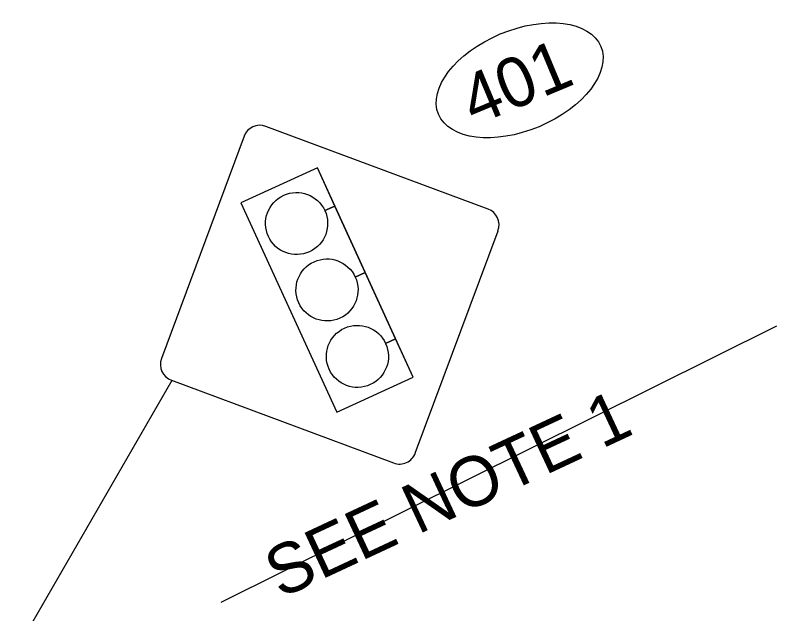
# Model space of a CAD drawing. Extents: x 2096670 to 2098561, y 684033 to 689893.
# Drawn here: x 2097982.4 to 2098166.2, y 685494.3 to 685638.7 of the extents above; entities that cross this region are included whole.
import ezdxf

# ---------------------------------------------------------------- set-up
doc = ezdxf.new("R2010")
doc.units = 0
for name, color, linetype in [('Prop DSN Text', 7, 'Continuous'), ('Prop Sign E One Way_Right CELL', 7, 'Continuous'), ('Prop Sign E Signal Light Ahead CELL', 7, 'Continuous'), ('Scratch_Level_3', 7, 'Continuous')]:
    doc.layers.add(name, color=color, linetype=linetype)

msp = doc.modelspace()

# ---------------------------------------------------------------- linework, layer by layer
at = {"layer": 'Prop Sign E One Way_Right CELL'}
msp.add_ellipse((2098104.11, 685623.02), major_axis=(-19.58, -8.19), ratio=0.571429, dxfattribs=at)
at = {"layer": 'Prop Sign E Signal Light Ahead CELL'}
for p, q in [((2098096.47, 685591.96), (2098042.84, 685611.91)), ((2098037.6, 685609.51), (2098017.65, 685555.88)), ((2098078.92, 685533.08), (2098098.88, 685586.71)), ((2098071.76, 685559.52), (2098071.76, 685559.52)), ((2098071.76, 685559.52), (2098071.76, 685559.52)), ((2098020.18, 685550.58), (2097970.73, 685464.96)), ((2098020.05, 685550.63), (2098073.68, 685530.68))]:
    msp.add_line(p, q, dxfattribs=at)
msp.add_lwpolyline([(2098059.94, 685542.96), (2098078.38, 685551.4), (2098055.27, 685601.9), (2098036.83, 685593.46)], close=True, dxfattribs=at)
for points in [[(2098057.08, 685591.58), (2098059.48, 685592.68), (2098055.27, 685601.9), (2098036.83, 685593.46), (2098059.94, 685542.96), (2098078.38, 685551.4), (2098074.16, 685560.62), (2098071.76, 685559.52)], [(2098057.08, 685591.58), (2098059.48, 685592.68), (2098055.27, 685601.9), (2098036.83, 685593.46), (2098059.94, 685542.96), (2098078.38, 685551.4), (2098074.16, 685560.62), (2098071.76, 685559.52)], [(2098064.42, 685575.55), (2098066.82, 685576.65), (2098059.48, 685592.68), (2098057.08, 685591.58)], [(2098064.42, 685575.55), (2098066.82, 685576.65), (2098059.48, 685592.68), (2098057.08, 685591.58)], [(2098071.76, 685559.52), (2098074.16, 685560.62), (2098066.82, 685576.65), (2098064.42, 685575.55)], [(2098071.76, 685559.52), (2098074.16, 685560.62), (2098066.82, 685576.65), (2098064.42, 685575.55)]]:
    msp.add_lwpolyline(points, dxfattribs=at)
for centre, major_axis, start_param, end_param in [((2098041.42, 685608.09), (-1.7, 3.71), 5.497787, 7.068583), ((2098050.27, 685588.46), (-3.12, 6.81), 4.712482, 10.995574), ((2098050.27, 685588.46), (-3.12, 6.81), 4.712482, 10.995574), ((2098095.05, 685588.13), (-1.7, 3.71), 3.926991, 5.497787), ((2098057.6, 685572.43), (-3.12, 6.81), 4.712482, 10.995574), ((2098057.6, 685572.43), (-3.12, 6.81), 4.712482, 10.995574), ((2098064.94, 685556.4), (-3.12, 6.81), 4.712482, 10.995574), ((2098064.94, 685556.4), (-3.12, 6.81), 4.712482, 10.995574), ((2098021.47, 685554.46), (-1.7, 3.71), 0.785398, 2.356194), ((2098075.1, 685534.5), (-1.7, 3.71), 2.356194, 3.926991)]:
    msp.add_ellipse(centre, major_axis=major_axis, ratio=0.999984, start_param=start_param, end_param=end_param, dxfattribs=at)
for centre in [(2098050.27, 685588.46), (2098050.27, 685588.46), (2098057.6, 685572.43), (2098057.6, 685572.43), (2098064.94, 685556.4)]:
    msp.add_ellipse(centre, major_axis=(-3.12, 6.81), ratio=0.999984, dxfattribs=at)
at = {"layer": 'Scratch_Level_3'}
msp.add_line((2098032.02, 685497.08), (2098166.16, 685563.79), dxfattribs=at)

# ---------------------------------------------------------------- texts
at = {"layer": 'Prop DSN Text'}
msp.add_text('SEE NOTE 1', height=12, rotation=25.0045, dxfattribs=at).set_placement((2098046.38, 685497.88))
at = {"layer": 'Prop Sign E One Way_Right CELL'}
msp.add_text('401', height=11.98, rotation=22.6926, dxfattribs=at).set_placement((2098093.16, 685611.95))

doc.saveas('drawing.dxf')
